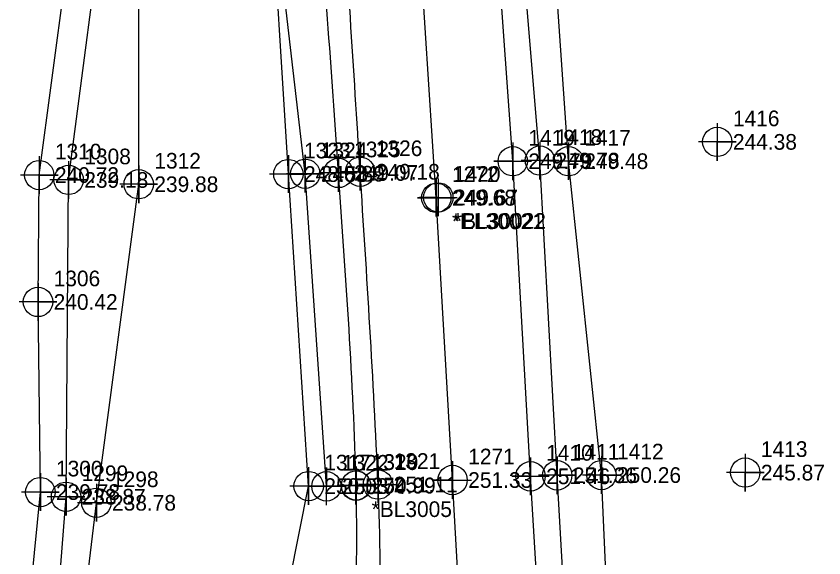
# Model space of a CAD drawing. Extents: x 2130962 to 2131465, y 643052 to 644206.
# Drawn here: x 2131170.6 to 2131299.6, y 643306.2 to 643392.7 of the extents above; entities that cross this region are included whole.
import ezdxf

# ---------------------------------------------------------------- set-up
doc = ezdxf.new("R2010")
doc.units = 0
for name, color, linetype in [('Exist DTM Breakline', 7, 'Continuous'), ('Exist DTM Breakline Cogo Elevation', 7, 'Continuous'), ('Exist DTM Breakline Cogo Number', 7, 'Continuous'), ('Exist DTM Breakline Cogo Point CELL', 7, 'Continuous'), ('Exist DTM Drainline', 7, 'Continuous'), ('Exist DTM Drainline Cogo Elevation', 7, 'Continuous'), ('Exist DTM Drainline Cogo Number', 7, 'Continuous'), ('Exist DTM Drainline Cogo Point CELL', 7, 'Continuous'), ('Exist DTM Regular Point CELL', 7, 'Continuous'), ('Exist DTM Regular Point Cogo Elevation', 7, 'Continuous'), ('Exist DTM Regular Point Cogo Number', 7, 'Continuous'), ('Exist Roads EOP', 7, 'Continuous'), ('Exist Roads EOP Cogo Elevation', 7, 'Continuous'), ('Exist Roads EOP Cogo Number', 7, 'Continuous'), ('Exist Roads EOP Cogo Point CELL', 7, 'Continuous'), ('Exist Roads EOT', 7, 'Continuous'), ('Exist Roads EOT Cogo Comment', 7, 'Continuous'), ('Exist Roads EOT Cogo Elevation', 7, 'Continuous'), ('Exist Roads EOT Cogo Number', 7, 'Continuous'), ('Exist Roads EOT Cogo Point CELL', 7, 'Continuous'), ('Exist Roads Soil', 7, 'Continuous'), ('Exist Roads Soil Cogo Comment', 7, 'Continuous'), ('Exist Roads Soil Cogo Elevation', 7, 'Continuous'), ('Exist Roads Soil Cogo Number', 7, 'Continuous'), ('Exist Roads Soil Cogo Point CELL', 7, 'Continuous')]:
    doc.layers.add(name, color=color, linetype=linetype)

msp = doc.modelspace()

# ---------------------------------------------------------------- linework, layer by layer
at = {"layer": 'Exist DTM Breakline'}
for points in [[(2131266.3306, 643269.372), (2131264.0776, 643319.4437), (2131258.8396, 643369.5498), (2131255.3671, 643419.5794), (2131249.6414, 643469.556), (2131244.7652, 643520.0623), (2131238.8778, 643569.4077), (2131228.6495, 643620.6699), (2131219.85, 643669.4823), (2131206.9682, 643717.8453), (2131195.8132, 643768.1497), (2131183.2404, 643816.8151), (2131169.0496, 643865.1461), (2131151.2314, 643913.4424), (2131130.7295, 643958.9736), (2131122.7411, 643983.0115)], [(2131000.7408, 643235.0731), (2131050.2503, 643235.0771), (2131099.3971, 643233.3967), (2131102.4734, 643233.467), (2131117.9784, 643240.6457), (2131141.4902, 643260.2289), (2131148.9668, 643267.309), (2131161.3925, 643274.3195), (2131169.1458, 643283.2692), (2131172.0772, 643292.493), (2131174.434, 643316.7319), (2131174.0607, 643347.0813), (2131174.2633, 643367.3367), (2131180.4607, 643413.966), (2131183.0424, 643464.7744), (2131179.7562, 643510.5479), (2131157.5016, 643561.2065), (2131139.0887, 643604.6918), (2131124.996, 643650.6897)], [(2131000.2707, 643222.2884), (2131049.3172, 643219.2511), (2131099.5024, 643216.1866), (2131123.0232, 643217.8518), (2131146.7721, 643223.5416), (2131166.8509, 643229.4959), (2131199.4918, 643255.6512), (2131208.4065, 643272.9132), (2131217.3052, 643317.6851), (2131214.0619, 643367.4973), (2131211.0353, 643416.1836)]]:
    msp.add_lwpolyline(points, dxfattribs=at)
at = {"layer": 'Exist DTM Breakline Cogo Point CELL'}
for points in [[(2131258.8396, 643372.5498), (2131258.8396, 643366.5498), (2131258.8396, 643369.5498), (2131261.8396, 643369.5498), (2131255.8396, 643369.5498)], [(2131174.2633, 643370.3367), (2131174.2633, 643364.3367), (2131174.2633, 643367.3367), (2131177.2633, 643367.3367), (2131171.2633, 643367.3367)], [(2131214.0619, 643370.4973), (2131214.0619, 643364.4973), (2131214.0619, 643367.4973), (2131217.0619, 643367.4973), (2131211.0619, 643367.4973)], [(2131174.0607, 643350.0813), (2131174.0607, 643344.0813), (2131174.0607, 643347.0813), (2131177.0607, 643347.0813), (2131171.0607, 643347.0813)], [(2131264.0776, 643322.4437), (2131264.0776, 643316.4437), (2131264.0776, 643319.4437), (2131267.0776, 643319.4437), (2131261.0776, 643319.4437)], [(2131174.434, 643319.7319), (2131174.434, 643313.7319), (2131174.434, 643316.7319), (2131177.434, 643316.7319), (2131171.434, 643316.7319)], [(2131217.3052, 643320.6851), (2131217.3052, 643314.6851), (2131217.3052, 643317.6851), (2131220.3052, 643317.6851), (2131214.3052, 643317.6851)]]:
    msp.add_lwpolyline(points, dxfattribs=at)
for centre in [(2131258.8396, 643369.5498), (2131174.2633, 643367.3367), (2131214.0619, 643367.4973), (2131174.0607, 643347.0813), (2131264.0776, 643319.4437), (2131217.3052, 643317.6851), (2131174.434, 643316.7319)]:
    msp.add_circle(centre, 2.344, dxfattribs=at)
at = {"layer": 'Exist DTM Drainline'}
for points in [[(2131000.2029, 643226.7228), (2131050.9884, 643228.9032), (2131099.0297, 643228.5605), (2131120.2968, 643239.3591), (2131144.9156, 643253.3469), (2131146.4739, 643252.3674), (2131154.3188, 643256.8046), (2131168.9618, 643265.5132), (2131176.6257, 643272.964), (2131179.8144, 643285.303), (2131183.3842, 643315.022), (2131190.1471, 643365.8731), (2131190.1489, 643413.686), (2131192.3886, 643466.4632), (2131188.8083, 643512.615), (2131184.0059, 643563.7066), (2131175.3, 643610.7482), (2131168.3784, 643658.7431), (2131156.7476, 643707.4708), (2131144.9036, 643754.0458), (2131132.9438, 643802.544), (2131118.0831, 643847.9475), (2131104.0084, 643896.8663), (2131096.3866, 643919.4077)], [(2131149.8388, 643262.7067), (2131163.2746, 643268.7404), (2131165.1512, 643269.4553), (2131171.0778, 643276.7299), (2131176.4073, 643288.8357), (2131178.5355, 643315.9841), (2131178.9558, 643366.5567), (2131185.1892, 643414.0962), (2131192.3516, 643466.0067)]]:
    msp.add_lwpolyline(points, dxfattribs=at)
at = {"layer": 'Exist DTM Drainline Cogo Point CELL'}
for points in [[(2131178.9558, 643369.5567), (2131178.9558, 643363.5567), (2131178.9558, 643366.5567), (2131181.9558, 643366.5567), (2131175.9558, 643366.5567)], [(2131190.1471, 643368.8731), (2131190.1471, 643362.8731), (2131190.1471, 643365.8731), (2131193.1471, 643365.8731), (2131187.1471, 643365.8731)], [(2131178.5355, 643318.9841), (2131178.5355, 643312.9841), (2131178.5355, 643315.9841), (2131181.5355, 643315.9841), (2131175.5355, 643315.9841)], [(2131183.3842, 643318.022), (2131183.3842, 643312.022), (2131183.3842, 643315.022), (2131186.3842, 643315.022), (2131180.3842, 643315.022)]]:
    msp.add_lwpolyline(points, dxfattribs=at)
for centre in [(2131178.9558, 643366.5567), (2131190.1471, 643365.8731), (2131178.5355, 643315.9841), (2131183.3842, 643315.022)]:
    msp.add_circle(centre, 2.344, dxfattribs=at)
at = {"layer": 'Exist DTM Regular Point CELL'}
for points in [[(2131282.5896, 643375.6339), (2131282.5896, 643369.6339), (2131282.5896, 643372.6339), (2131285.5896, 643372.6339), (2131279.5896, 643372.6339)], [(2131287.0602, 643322.8402), (2131287.0602, 643316.8402), (2131287.0602, 643319.8402), (2131290.0602, 643319.8402), (2131284.0602, 643319.8402)]]:
    msp.add_lwpolyline(points, dxfattribs=at)
for centre in [(2131282.5896, 643372.6339), (2131287.0602, 643319.8402)]:
    msp.add_circle(centre, 2.344, dxfattribs=at)
at = {"layer": 'Exist Roads EOP'}
msp.add_lwpolyline([(2131264.2715, 643222.5647), (2131259.8757, 643269.3254), (2131257.0196, 643319.4043), (2131254.2561, 643369.6499), (2131250.0777, 643419.4187), (2131246.1511, 643469.0294), (2131240.8382, 643519.1271), (2131234.3674, 643568.5584), (2131226.3321, 643620.1808), (2131217.0271, 643668.7116), (2131205.6213, 643717.607), (2131192.0578, 643767.2595), (2131177.9714, 643815.0911), (2131162.2913, 643862.9344), (2131145.3604, 643910.8486), (2131126.9113, 643957.2915), (2131112.3691, 643996.1228)], dxfattribs=at)
msp.add_spline([(2131166.2495, 643216.6951), (2131171.8131, 643218.7244), (2131182.3713, 643223.9726), (2131191.8117, 643231.1489), (2131200.5013, 643239.6993), (2131208.8071, 643249.0697), (2131216.0672, 643259.0032), (2131218.7188, 643264.347), (2131220.5363, 643270.0958), (2131222.8445, 643282.0077), (2131224.3583, 643293.9245), (2131224.8763, 643317.7904), (2131222.0632, 643367.6716), (2131218.5448, 643416.8114), (2131214.3187, 643466.3462), (2131209.1735, 643515.6666), (2131202.7939, 643565.1545), (2131195.0475, 643613.9937), (2131186.4014, 643662.4763), (2131176.0113, 643711.405), (2131164.6154, 643759.8896), (2131151.874, 643807.8526), (2131137.8554, 643855.4065), (2131122.5733, 643902.8574), (2131105.9622, 643949.4862), (2131091.5349, 643988.0437)], degree=3, dxfattribs=at)
at = {"layer": 'Exist Roads EOP Cogo Point CELL'}
for points in [[(2131254.2561, 643372.6499), (2131254.2561, 643366.6499), (2131254.2561, 643369.6499), (2131257.2561, 643369.6499), (2131251.2561, 643369.6499)], [(2131222.0632, 643370.6716), (2131222.0632, 643364.6716), (2131222.0632, 643367.6716), (2131225.0632, 643367.6716), (2131219.0632, 643367.6716)], [(2131257.0196, 643322.4043), (2131257.0196, 643316.4043), (2131257.0196, 643319.4043), (2131260.0196, 643319.4043), (2131254.0196, 643319.4043)], [(2131224.8763, 643320.7904), (2131224.8763, 643314.7904), (2131224.8763, 643317.7904), (2131227.8763, 643317.7904), (2131221.8763, 643317.7904)]]:
    msp.add_lwpolyline(points, dxfattribs=at)
for centre in [(2131254.2561, 643369.6499), (2131222.0632, 643367.6716), (2131257.0196, 643319.4043), (2131224.8763, 643317.7904)]:
    msp.add_circle(centre, 2.344, dxfattribs=at)
at = {"layer": 'Exist Roads EOT'}
for points in [[(2131255.7894, 643269.2666), (2131252.7511, 643319.2443), (2131249.9083, 643369.5477), (2131246.3502, 643419.1778), (2131242.1933, 643468.6938), (2131237.0867, 643518.9193), (2131230.8671, 643568.2588), (2131222.7066, 643619.1047), (2131213.6442, 643668.3078), (2131202.755, 643717.0933), (2131189.234, 643766.4577), (2131174.9499, 643814.1787), (2131159.2111, 643861.933), (2131141.9103, 643909.6722), (2131123.7008, 643956.0828), (2131104.9436, 644003.1503), (2131086.2706, 644048.8072), (2131065.6997, 644094.9191), (2131044.3618, 644140.0645), (2131021.6804, 644185.4526)], [(2131237.6994, 643363.706), (2131234.1644, 643418.0043), (2131229.8934, 643468.0098), (2131225.1139, 643518.3873), (2131218.7748, 643566.6133), (2131210.7043, 643617.3811), (2131201.4139, 643666.7928), (2131191.4121, 643714.0755), (2131179.6696, 643764.3904), (2131167.3006, 643812.1237), (2131153.7359, 643860.4033), (2131138.3711, 643908.8544), (2131125.1607, 643951.4161)], [(2131240.2947, 643263.0991), (2131242.6265, 643277.2895), (2131240.2984, 643318.6562), (2131237.6994, 643363.706)]]:
    msp.add_lwpolyline(points, dxfattribs=at)
msp.add_spline([(2131166.718, 643215.2083), (2131172.3866, 643217.1804), (2131211.4056, 643247.1499), (2131223.758, 643268.7314), (2131228.3848, 643317.935), (2131225.533, 643367.8628), (2131222.2486, 643417.1873), (2131217.9619, 643466.6275), (2131212.8794, 643516.2377), (2131206.5633, 643565.5764), (2131198.9021, 643614.6757), (2131189.6851, 643663.4055), (2131179.3985, 643712.1311), (2131168.3085, 643760.7185), (2131155.755, 643808.9129), (2131141.6748, 643856.5528), (2131126.5354, 643904.2758), (2131110.3559, 643951.0191), (2131092.4533, 643998.1348), (2131073.722, 644043.631), (2131053.1654, 644089.359), (2131032.0052, 644134.0908), (2131009.0644, 644179.3802)], degree=3, dxfattribs=at)
at = {"layer": 'Exist Roads EOT Cogo Point CELL'}
for points in [[(2131249.9083, 643372.5477), (2131249.9083, 643366.5477), (2131249.9083, 643369.5477), (2131246.9083, 643369.5477), (2131252.9083, 643369.5477)], [(2131225.533, 643370.8628), (2131225.533, 643364.8628), (2131225.533, 643367.8628), (2131222.533, 643367.8628), (2131228.533, 643367.8628)], [(2131237.6994, 643366.706), (2131237.6994, 643360.706), (2131237.6994, 643363.706), (2131234.6994, 643363.706), (2131240.6994, 643363.706)], [(2131238.0214, 643366.7668), (2131238.0214, 643360.7668), (2131238.0214, 643363.7668), (2131235.0214, 643363.7668), (2131241.0214, 643363.7668)], [(2131252.7511, 643322.2443), (2131252.7511, 643316.2443), (2131252.7511, 643319.2443), (2131249.7511, 643319.2443), (2131255.7511, 643319.2443)], [(2131228.3848, 643320.935), (2131228.3848, 643314.935), (2131228.3848, 643317.935), (2131225.3848, 643317.935), (2131231.3848, 643317.935)], [(2131240.2984, 643321.6562), (2131240.2984, 643315.6562), (2131240.2984, 643318.6562), (2131237.2984, 643318.6562), (2131243.2984, 643318.6562)]]:
    msp.add_lwpolyline(points, dxfattribs=at)
for centre in [(2131249.9083, 643369.5477), (2131225.533, 643367.8628), (2131238.0214, 643363.7668), (2131237.6994, 643363.706), (2131240.2984, 643318.6562), (2131252.7511, 643319.2443), (2131228.3848, 643317.935)]:
    msp.add_circle(centre, 2.344, dxfattribs=at)
at = {"layer": 'Exist Roads Soil'}
msp.add_lwpolyline([(2131224.8674, 643317.753), (2131220.141, 643317.6487), (2131216.7544, 643367.544), (2131211.084, 643416.163), (2131207.4344, 643466.363), (2131202.1097, 643514.7948), (2131195.0195, 643564.3052), (2131187.2605, 643612.6498), (2131179.506, 643660.9545), (2131164.8317, 643709.0781), (2131153.9175, 643755.9834), (2131140.8896, 643804.492), (2131127.2512, 643851.9231), (2131113.4771, 643899.8082), (2131083.6685, 643994.997), (2131066.191, 644040.9476), (2131049.1539, 644087.3869)], dxfattribs=at)
at = {"layer": 'Exist Roads Soil Cogo Point CELL'}
for points in [[(2131216.7544, 643364.544), (2131216.7544, 643370.544), (2131216.7544, 643367.544), (2131219.7544, 643367.544), (2131213.7544, 643367.544)], [(2131220.141, 643314.6487), (2131220.141, 643320.6487), (2131220.141, 643317.6487), (2131223.141, 643317.6487), (2131217.141, 643317.6487)], [(2131224.8674, 643314.753), (2131224.8674, 643320.753), (2131224.8674, 643317.753), (2131227.8674, 643317.753), (2131221.8674, 643317.753)]]:
    msp.add_lwpolyline(points, dxfattribs=at)
for centre in [(2131216.7544, 643367.544), (2131220.141, 643317.6487), (2131224.8674, 643317.753)]:
    msp.add_circle(centre, 2.344, dxfattribs=at)

# ---------------------------------------------------------------- texts
at = {"layer": 'Exist DTM Breakline Cogo Elevation'}
for s, p in [('249.48', (2131261.3396, 643368.2998)), ('248.58', (2131216.5619, 643366.2473)), ('240.72', (2131176.7633, 643366.0867)), ('240.42', (2131176.5607, 643345.8313)), ('250.26', (2131266.5776, 643318.1937)), ('250.53', (2131219.8052, 643316.4351)), ('239.78', (2131176.934, 643315.4819))]:
    msp.add_text(s, height=2.5, dxfattribs=at).set_placement(p)
at = {"layer": 'Exist DTM Breakline Cogo Number'}
for s, p in [('1417', (2131261.3396, 643372.0498)), ('1323', (2131216.5619, 643369.9973)), ('1310', (2131176.7633, 643369.8367)), ('1306', (2131176.5607, 643349.5813)), ('1412', (2131266.5776, 643321.9437)), ('1317', (2131219.8052, 643320.1851)), ('1300', (2131176.934, 643319.2319))]:
    msp.add_text(s, height=2.5, dxfattribs=at).set_placement(p)
at = {"layer": 'Exist DTM Drainline Cogo Elevation'}
for s, p in [('239.18', (2131181.4558, 643365.3067)), ('239.88', (2131192.6471, 643364.6231)), ('238.87', (2131181.0355, 643314.7341)), ('238.78', (2131185.8842, 643313.772))]:
    msp.add_text(s, height=2.5, dxfattribs=at).set_placement(p)
at = {"layer": 'Exist DTM Drainline Cogo Number'}
for s, p in [('1308', (2131181.4558, 643369.0567)), ('1312', (2131192.6471, 643368.3731)), ('1299', (2131181.0355, 643318.4841)), ('1298', (2131185.8842, 643317.522))]:
    msp.add_text(s, height=2.5, dxfattribs=at).set_placement(p)
at = {"layer": 'Exist DTM Regular Point Cogo Elevation'}
for s, p in [('244.38', (2131285.0896, 643371.3839)), ('245.87', (2131289.5602, 643318.5902))]:
    msp.add_text(s, height=2.5, dxfattribs=at).set_placement(p)
at = {"layer": 'Exist DTM Regular Point Cogo Number'}
for s, p in [('1416', (2131285.0896, 643375.1339)), ('1413', (2131289.5602, 643322.3402))]:
    msp.add_text(s, height=2.5, dxfattribs=at).set_placement(p)
at = {"layer": 'Exist Roads EOP Cogo Elevation'}
for s, p in [('249.78', (2131256.7561, 643368.3999)), ('249.07', (2131224.5632, 643366.4216)), ('251.36', (2131259.5196, 643318.1543)), ('250.99', (2131227.3763, 643316.5404))]:
    msp.add_text(s, height=2.5, dxfattribs=at).set_placement(p)
at = {"layer": 'Exist Roads EOP Cogo Number'}
for s, p in [('1418', (2131256.7561, 643372.1499)), ('1325', (2131224.5632, 643370.1716)), ('1411', (2131259.5196, 643321.9043)), ('1319', (2131227.3763, 643320.2904))]:
    msp.add_text(s, height=2.5, dxfattribs=at).set_placement(p)
at = {"layer": 'Exist Roads EOT Cogo Comment'}
for s, p in [('*EL30021', (2131240.1994, 643358.706)), ('*BL30022', (2131240.5214, 643358.7668))]:
    msp.add_text(s, height=2.5, dxfattribs=at).set_placement(p)
at = {"layer": 'Exist Roads EOT Cogo Elevation'}
for s, p in [('249.79', (2131252.4083, 643368.2977)), ('249.18', (2131228.033, 643366.6128)), ('249.68', (2131240.1994, 643362.456)), ('249.67', (2131240.5214, 643362.5168)), ('251.33', (2131242.7984, 643317.4062)), ('251.46', (2131255.2511, 643317.9943)), ('251.11', (2131230.8848, 643316.685))]:
    msp.add_text(s, height=2.5, dxfattribs=at).set_placement(p)
at = {"layer": 'Exist Roads EOT Cogo Number'}
for s, p in [('1419', (2131252.4083, 643372.0477)), ('1326', (2131228.033, 643370.3628)), ('1272', (2131240.1994, 643366.206)), ('1420', (2131240.5214, 643366.2668)), ('1271', (2131242.7984, 643321.1562)), ('1410', (2131255.2511, 643321.7443)), ('1321', (2131230.8848, 643320.435))]:
    msp.add_text(s, height=2.5, dxfattribs=at).set_placement(p)
at = {"layer": 'Exist Roads Soil Cogo Comment'}
msp.add_text('*BL3005', height=2.5, dxfattribs=at).set_placement((2131227.3674, 643312.753))
at = {"layer": 'Exist Roads Soil Cogo Elevation'}
for s, p in [('248.89', (2131219.2544, 643366.294)), ('250.74', (2131222.641, 643316.3987)), ('250.99', (2131227.3674, 643316.503))]:
    msp.add_text(s, height=2.5, dxfattribs=at).set_placement(p)
at = {"layer": 'Exist Roads Soil Cogo Number'}
for s, p in [('1324', (2131219.2544, 643370.044)), ('1322', (2131222.641, 643320.1487)), ('1320', (2131227.3674, 643320.253))]:
    msp.add_text(s, height=2.5, dxfattribs=at).set_placement(p)

doc.saveas('drawing.dxf')
